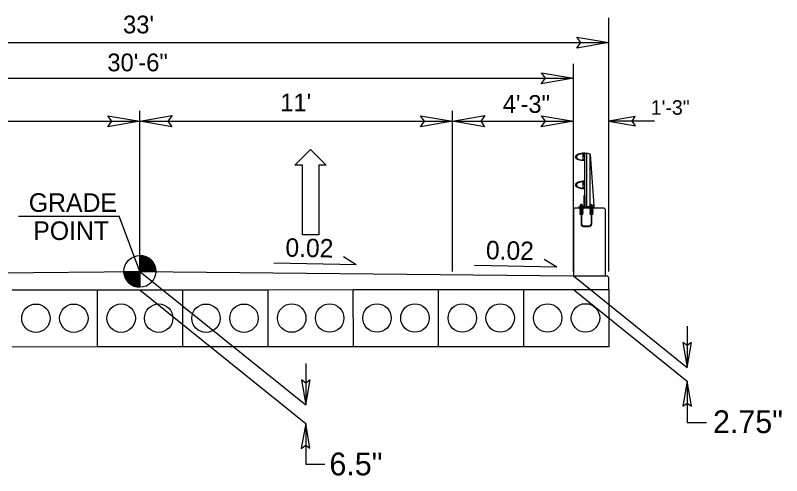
# Model space of a CAD drawing. Extents: x 1733676 to 1734289, y 540979 to 541226.
# Drawn here: x 1734262.38 to 1734289.33, y 541078.06 to 541094.25 of the extents above; entities that cross this region are included whole.
import ezdxf

# ---------------------------------------------------------------- set-up
doc = ezdxf.new("R2010")
doc.units = 0
for name, color, linetype in [('Prop Dimension', 7, 'Continuous'), ('Prop Lane Arrow CELL', 7, 'Continuous'), ('Prop Terminator CELL', 7, 'Continuous'), ('Typical Bridge Rail Two Bar CELL', 7, 'Continuous'), ('Typical Grade Point Symbol CELL', 7, 'Continuous'), ('Typical Pavement Slope CELL', 7, 'Continuous'), ('Typical Pavement Slope Information CELL', 7, 'Continuous'), ('Typical Slope Point Local CELL', 7, 'Continuous'), ('Typical Terminator CELL', 7, 'Continuous'), ('Typical Text Grade Point CELL', 7, 'Continuous')]:
    doc.layers.add(name, color=color, linetype=linetype)

msp = doc.modelspace()

# ---------------------------------------------------------------- linework, layer by layer
at = {"layer": 'Prop Dimension'}
for p, q in [((1734283.259, 541085.248), (1734283.259, 541094.168)), ((1734250.259, 541093.296), (1734283.259, 541093.296)), ((1734282.009, 541085.248), (1734282.009, 541092.543)), ((1734251.509, 541092.043), (1734282.009, 541092.043)), ((1734266.759, 541085.248), (1734266.759, 541090.891)), ((1734277.759, 541085.248), (1734277.759, 541090.891)), ((1734255.759, 541090.531), (1734266.759, 541090.531)), ((1734266.759, 541090.531), (1734277.759, 541090.531)), ((1734277.759, 541090.531), (1734282.009, 541090.531)), ((1734284.864, 541090.531), (1734283.259, 541090.531)), ((1734262.486, 541087.185), (1734266.024, 541087.185)), ((1734266.759, 541085.248), (1734266.024, 541087.185)), ((1734266.759, 541085.248), (1734272.591, 541080.549)), ((1734282.009, 541085.092), (1734286.01, 541081.869)), ((1734262.266, 541084.599), (1734265.266, 541084.601)), ((1734265.266, 541084.601), (1734268.266, 541084.603)), ((1734265.267, 541082.601), (1734265.266, 541084.601)), ((1734265.267, 541082.601), (1734265.266, 541084.601)), ((1734266.759, 541084.602), (1734272.591, 541079.903)), ((1734268.266, 541084.603), (1734271.266, 541084.604)), ((1734268.267, 541082.603), (1734268.266, 541084.603)), ((1734268.267, 541082.603), (1734268.266, 541084.603)), ((1734271.266, 541084.604), (1734274.266, 541084.606)), ((1734271.267, 541082.604), (1734271.266, 541084.604)), ((1734271.267, 541082.604), (1734271.266, 541084.604)), ((1734274.266, 541084.606), (1734277.266, 541084.608)), ((1734274.267, 541082.606), (1734274.266, 541084.606)), ((1734274.267, 541082.606), (1734274.266, 541084.606)), ((1734277.266, 541084.608), (1734280.266, 541084.61)), ((1734277.267, 541082.608), (1734277.266, 541084.608)), ((1734277.267, 541082.608), (1734277.266, 541084.608)), ((1734280.266, 541084.61), (1734283.266, 541084.611)), ((1734280.267, 541082.61), (1734280.266, 541084.61)), ((1734280.267, 541082.61), (1734280.266, 541084.61)), ((1734282.009, 541084.611), (1734286.01, 541081.387)), ((1734283.267, 541082.611), (1734283.266, 541084.611)), ((1734286.01, 541083.321), (1734286.01, 541081.869)), ((1734262.267, 541082.599), (1734265.267, 541082.601)), ((1734265.267, 541082.601), (1734268.267, 541082.603)), ((1734268.267, 541082.603), (1734271.267, 541082.604)), ((1734271.267, 541082.604), (1734274.267, 541082.606)), ((1734274.267, 541082.606), (1734277.267, 541082.608)), ((1734277.267, 541082.608), (1734280.267, 541082.61)), ((1734280.267, 541082.61), (1734283.267, 541082.611)), ((1734272.591, 541082.002), (1734272.591, 541080.549)), ((1734286.01, 541081.387), (1734286.01, 541079.935)), ((1734272.591, 541079.903), (1734272.591, 541078.45)), ((1734286.01, 541079.935), (1734286.687, 541079.935)), ((1734273.268, 541078.45), (1734272.591, 541078.45))]:
    msp.add_line(p, q, dxfattribs=at)
for centre in [(1734263.1, 541083.6), (1734264.433, 541083.6), (1734266.1, 541083.601), (1734267.418, 541083.601), (1734269.085, 541083.6), (1734270.418, 541083.6), (1734272.1, 541083.605), (1734273.433, 541083.606), (1734275.1, 541083.607), (1734276.433, 541083.607), (1734278.1, 541083.608), (1734279.433, 541083.609), (1734281.1, 541083.61), (1734282.433, 541083.611)]:
    msp.add_circle(centre, 0.5, dxfattribs=at)
at = {"layer": 'Prop Lane Arrow CELL'}
for p, q in [((1734272.213, 541088.984), (1734272.755, 541089.536)), ((1734272.755, 541089.536), (1734273.315, 541088.984)), ((1734272.475, 541088.984), (1734272.213, 541088.984)), ((1734272.475, 541086.534), (1734272.475, 541088.984)), ((1734273.315, 541088.984), (1734273.053, 541088.984)), ((1734273.053, 541088.984), (1734273.053, 541086.534)), ((1734273.053, 541086.534), (1734272.475, 541086.534))]:
    msp.add_line(p, q, dxfattribs=at)
at = {"layer": 'Prop Terminator CELL'}
for points in [[(1734282.134, 541093.489), (1734283.259, 541093.296), (1734282.128, 541093.096), (1734282.271, 541093.296)], [(1734280.884, 541092.236), (1734282.009, 541092.043), (1734280.878, 541091.843), (1734281.021, 541092.043)], [(1734265.634, 541090.725), (1734266.759, 541090.531), (1734265.628, 541090.331), (1734265.771, 541090.531)], [(1734267.884, 541090.338), (1734266.759, 541090.531), (1734267.89, 541090.731), (1734267.746, 541090.531)], [(1734276.634, 541090.725), (1734277.759, 541090.531), (1734276.628, 541090.331), (1734276.771, 541090.531)], [(1734278.884, 541090.338), (1734277.759, 541090.531), (1734278.89, 541090.731), (1734278.746, 541090.531)], [(1734280.884, 541090.725), (1734282.009, 541090.531), (1734280.878, 541090.331), (1734281.021, 541090.531)], [(1734284.184, 541090.691), (1734283.259, 541090.531), (1734284.19, 541090.367), (1734284.071, 541090.531)]]:
    msp.add_lwpolyline(points, close=True, dxfattribs=at)
at = {"layer": 'Typical Bridge Rail Two Bar CELL'}
for p, q in [((1734282.346, 541089.377), (1734282.346, 541089.275)), ((1734282.409, 541089.409), (1734282.484, 541089.409)), ((1734282.409, 541087.525), (1734282.409, 541089.409)), ((1734282.598, 541089.371), (1734282.484, 541089.409)), ((1734282.484, 541087.525), (1734282.484, 541089.409)), ((1734282.598, 541087.525), (1734282.598, 541089.371)), ((1734282.598, 541089.371), (1734282.729, 541087.563)), ((1734282.346, 541089.173), (1734282.346, 541089.275)), ((1734282.598, 541088.507), (1734282.602, 541088.507)), ((1734282.346, 541088.39), (1734282.346, 541088.288)), ((1734282.346, 541088.186), (1734282.346, 541088.288)), ((1734282.01, 541087.439), (1734282.059, 541087.487)), ((1734282.01, 541087.439), (1734282.01, 541085.094)), ((1734282.059, 541087.487), (1734283.079, 541087.487)), ((1734282.237, 541087.451), (1734282.337, 541087.451)), ((1734282.237, 541087.44), (1734282.337, 541087.44)), ((1734282.237, 541087.407), (1734282.279, 541087.407)), ((1734282.237, 541087.396), (1734282.279, 541087.396)), ((1734282.259, 541087.429), (1734282.279, 541087.429)), ((1734282.259, 541087.418), (1734282.279, 541087.418)), ((1734282.262, 541087.451), (1734282.262, 541087.535)), ((1734282.264, 541087.576), (1734282.264, 541087.611)), ((1734282.264, 541087.611), (1734282.307, 541087.611)), ((1734282.279, 541087.429), (1734282.296, 541087.429)), ((1734282.279, 541087.429), (1734282.279, 541086.898)), ((1734282.296, 541087.429), (1734282.315, 541087.429)), ((1734282.296, 541087.429), (1734282.296, 541086.898)), ((1734282.296, 541087.418), (1734282.315, 541087.418)), ((1734282.296, 541087.407), (1734282.337, 541087.407)), ((1734282.296, 541087.396), (1734282.337, 541087.396)), ((1734282.307, 541087.611), (1734282.307, 541087.576)), ((1734282.309, 541087.451), (1734282.309, 541087.535)), ((1734282.586, 541087.451), (1734282.686, 541087.451)), ((1734282.586, 541087.44), (1734282.686, 541087.44)), ((1734282.586, 541087.407), (1734282.628, 541087.407)), ((1734282.586, 541087.396), (1734282.628, 541087.396)), ((1734282.608, 541087.429), (1734282.628, 541087.429)), ((1734282.608, 541087.418), (1734282.628, 541087.418)), ((1734282.613, 541087.566), (1734282.613, 541087.601)), ((1734282.613, 541087.601), (1734282.656, 541087.601)), ((1734282.613, 541087.442), (1734282.613, 541087.525)), ((1734282.628, 541087.429), (1734282.644, 541087.429)), ((1734282.628, 541087.429), (1734282.628, 541086.898)), ((1734282.644, 541087.429), (1734282.664, 541087.429)), ((1734282.644, 541087.429), (1734282.644, 541086.898)), ((1734282.644, 541087.418), (1734282.664, 541087.418)), ((1734282.644, 541087.407), (1734282.686, 541087.407)), ((1734282.644, 541087.396), (1734282.686, 541087.396)), ((1734282.656, 541087.601), (1734282.656, 541087.566)), ((1734282.657, 541087.442), (1734282.657, 541087.525)), ((1734282.726, 541087.584), (1734282.726, 541087.617)), ((1734282.729, 541087.525), (1734282.729, 541087.563)), ((1734283.079, 541087.487), (1734283.128, 541087.439)), ((1734283.128, 541087.439), (1734283.128, 541085.094)), ((1734282.237, 541087.362), (1734282.279, 541087.362)), ((1734282.237, 541087.351), (1734282.279, 541087.351)), ((1734282.237, 541087.318), (1734282.279, 541087.318)), ((1734282.237, 541087.307), (1734282.279, 541087.307)), ((1734282.237, 541087.274), (1734282.279, 541087.274)), ((1734282.237, 541087.263), (1734282.279, 541087.263)), ((1734282.259, 541087.384), (1734282.279, 541087.384)), ((1734282.259, 541087.373), (1734282.279, 541087.373)), ((1734282.259, 541087.34), (1734282.279, 541087.34)), ((1734282.259, 541087.329), (1734282.279, 541087.329)), ((1734282.259, 541087.296), (1734282.279, 541087.296)), ((1734282.259, 541087.285), (1734282.279, 541087.285)), ((1734282.296, 541087.384), (1734282.315, 541087.384)), ((1734282.296, 541087.373), (1734282.315, 541087.373)), ((1734282.296, 541087.362), (1734282.337, 541087.362)), ((1734282.296, 541087.351), (1734282.337, 541087.351)), ((1734282.296, 541087.34), (1734282.315, 541087.34)), ((1734282.296, 541087.329), (1734282.315, 541087.329)), ((1734282.296, 541087.318), (1734282.337, 541087.318)), ((1734282.296, 541087.307), (1734282.337, 541087.307)), ((1734282.296, 541087.296), (1734282.315, 541087.296)), ((1734282.296, 541087.285), (1734282.315, 541087.285)), ((1734282.296, 541087.274), (1734282.337, 541087.274)), ((1734282.296, 541087.263), (1734282.337, 541087.263)), ((1734282.586, 541087.362), (1734282.628, 541087.362)), ((1734282.586, 541087.351), (1734282.628, 541087.351)), ((1734282.586, 541087.318), (1734282.628, 541087.318)), ((1734282.586, 541087.307), (1734282.628, 541087.307)), ((1734282.586, 541087.274), (1734282.628, 541087.274)), ((1734282.586, 541087.263), (1734282.628, 541087.263)), ((1734282.608, 541087.384), (1734282.628, 541087.384)), ((1734282.608, 541087.373), (1734282.628, 541087.373)), ((1734282.608, 541087.34), (1734282.628, 541087.34)), ((1734282.608, 541087.329), (1734282.628, 541087.329)), ((1734282.608, 541087.296), (1734282.628, 541087.296)), ((1734282.608, 541087.285), (1734282.628, 541087.285)), ((1734282.644, 541087.384), (1734282.664, 541087.384)), ((1734282.644, 541087.373), (1734282.664, 541087.373)), ((1734282.644, 541087.362), (1734282.686, 541087.362)), ((1734282.644, 541087.351), (1734282.686, 541087.351)), ((1734282.644, 541087.34), (1734282.664, 541087.34)), ((1734282.644, 541087.329), (1734282.664, 541087.329)), ((1734282.644, 541087.318), (1734282.686, 541087.318)), ((1734282.644, 541087.307), (1734282.686, 541087.307)), ((1734282.644, 541087.296), (1734282.664, 541087.296)), ((1734282.644, 541087.285), (1734282.664, 541087.285)), ((1734282.644, 541087.274), (1734282.686, 541087.274)), ((1734282.644, 541087.263), (1734282.686, 541087.263)), ((1734282.349, 541086.845), (1734282.574, 541086.845)), ((1734282.349, 541086.829), (1734282.574, 541086.829)), ((1734282.01, 541085.094), (1734283.119, 541085.094)), ((1734283.119, 541085.094), (1734283.2, 541085.094)), ((1734283.248, 541085.041), (1734283.2, 541085.094))]:
    msp.add_line(p, q, dxfattribs=at)
for points in [[(1734282.409, 541089.145), (1734282.409, 541089.194), (1734282.389, 541089.194), (1734282.389, 541089.185), (1734282.39, 541089.185), (1734282.39, 541089.165), (1734282.358, 541089.165), (1734282.354, 541089.196), (1734282.354, 541089.275), (1734282.354, 541089.354), (1734282.358, 541089.385), (1734282.39, 541089.385), (1734282.39, 541089.365), (1734282.389, 541089.365), (1734282.389, 541089.357), (1734282.409, 541089.357), (1734282.409, 541089.406)], [(1734282.409, 541088.157), (1734282.409, 541088.206), (1734282.389, 541088.206), (1734282.389, 541088.198), (1734282.39, 541088.198), (1734282.39, 541088.178), (1734282.358, 541088.178), (1734282.354, 541088.209), (1734282.354, 541088.288), (1734282.354, 541088.367), (1734282.358, 541088.398), (1734282.39, 541088.398), (1734282.39, 541088.378), (1734282.389, 541088.378), (1734282.389, 541088.37), (1734282.409, 541088.37), (1734282.409, 541088.418)], [(1734282.216, 541087.487), (1734282.216, 541087.535), (1734282.39, 541087.535), (1734282.39, 541087.921), (1734282.409, 541087.921), (1734282.409, 541087.525), (1734282.72, 541087.525), (1734282.72, 541087.553), (1734282.729, 541087.553), (1734282.729, 541087.487), (1734282.579, 541087.487), (1734282.579, 541087.514), (1734282.428, 541087.514), (1734282.428, 541087.487), (1734282.216, 541087.487)], [(1734282.237, 541087.451), (1734282.237, 541087.44), (1734282.259, 541087.429), (1734282.259, 541087.418), (1734282.237, 541087.407), (1734282.237, 541087.396), (1734282.259, 541087.384), (1734282.259, 541087.373), (1734282.237, 541087.362), (1734282.237, 541087.351), (1734282.259, 541087.34), (1734282.259, 541087.329), (1734282.237, 541087.318), (1734282.237, 541087.307), (1734282.259, 541087.296), (1734282.259, 541087.285), (1734282.237, 541087.274), (1734282.237, 541087.263)], [(1734282.242, 541087.534), (1734282.242, 541087.543), (1734282.285, 541087.543), (1734282.328, 541087.543), (1734282.328, 541087.534)], [(1734282.254, 541087.543), (1734282.254, 541087.57), (1734282.259, 541087.575), (1734282.312, 541087.575), (1734282.318, 541087.57), (1734282.318, 541087.543), (1734282.254, 541087.543), (1734282.275, 541087.543), (1734282.275, 541087.57), (1734282.27, 541087.575), (1734282.275, 541087.57), (1734282.28, 541087.575), (1734282.292, 541087.575), (1734282.297, 541087.57), (1734282.297, 541087.543), (1734282.297, 541087.57), (1734282.302, 541087.575)], [(1734282.337, 541087.451), (1734282.337, 541087.44), (1734282.315, 541087.429), (1734282.315, 541087.418), (1734282.337, 541087.407), (1734282.337, 541087.396), (1734282.315, 541087.384), (1734282.315, 541087.373), (1734282.337, 541087.362), (1734282.337, 541087.351), (1734282.315, 541087.34), (1734282.315, 541087.329), (1734282.337, 541087.318), (1734282.337, 541087.307), (1734282.315, 541087.296), (1734282.315, 541087.285), (1734282.337, 541087.274), (1734282.337, 541087.263)], [(1734282.586, 541087.451), (1734282.586, 541087.44), (1734282.608, 541087.429), (1734282.608, 541087.418), (1734282.586, 541087.407), (1734282.586, 541087.396), (1734282.608, 541087.384), (1734282.608, 541087.373), (1734282.586, 541087.362), (1734282.586, 541087.351), (1734282.608, 541087.34), (1734282.608, 541087.329), (1734282.586, 541087.318), (1734282.586, 541087.307), (1734282.608, 541087.296), (1734282.608, 541087.285), (1734282.586, 541087.274), (1734282.586, 541087.263)], [(1734282.592, 541087.525), (1734282.592, 541087.533), (1734282.635, 541087.533), (1734282.678, 541087.533), (1734282.678, 541087.525)], [(1734282.603, 541087.533), (1734282.603, 541087.56), (1734282.608, 541087.566), (1734282.661, 541087.566), (1734282.667, 541087.56), (1734282.667, 541087.533), (1734282.603, 541087.533), (1734282.624, 541087.533), (1734282.624, 541087.56), (1734282.619, 541087.566), (1734282.624, 541087.56), (1734282.629, 541087.566), (1734282.64, 541087.566), (1734282.646, 541087.56), (1734282.646, 541087.533), (1734282.646, 541087.56), (1734282.651, 541087.566)], [(1734282.686, 541087.451), (1734282.686, 541087.44), (1734282.664, 541087.429), (1734282.664, 541087.418), (1734282.686, 541087.407), (1734282.686, 541087.396), (1734282.664, 541087.384), (1734282.664, 541087.373), (1734282.686, 541087.362), (1734282.686, 541087.351), (1734282.664, 541087.34), (1734282.664, 541087.329), (1734282.686, 541087.318), (1734282.686, 541087.307), (1734282.664, 541087.296), (1734282.664, 541087.285), (1734282.686, 541087.274), (1734282.686, 541087.263)]]:
    msp.add_lwpolyline(points, dxfattribs=at)
for centre in [(1734282.246, 541087.29), (1734282.677, 541087.29)]:
    msp.add_circle(centre, 0.00834, dxfattribs=at)
for centre, radius, start, end in [((1734282.338, 541089.377), 0.00783, 0, 90), ((1734282.338, 541089.173), 0.00783, 270, 360), ((1734282.338, 541088.39), 0.00783, 0, 90), ((1734282.338, 541088.186), 0.00783, 270, 360), ((1734282.349, 541086.898), 0.07, 180, 270), ((1734282.349, 541086.898), 0.0534, 180, 270), ((1734282.574, 541086.898), 0.0534, 270, 0), ((1734282.574, 541086.898), 0.07, 270, 0)]:
    msp.add_arc(centre, radius, start, end, dxfattribs=at)
for centre, major_axis, ratio, start_param, end_param in [((1734282.409, 541089.275), (-0.334, 0), 0.39036, 4.712404, 6.283584), ((1734282.338, 541089.275), (-0.222, 0), 0.495501, 4.712489, 6.283652), ((1734282.409, 541089.275), (-0.334, 0), 0.39036, 0.000398, 1.570782), ((1734282.338, 541089.275), (-0.222, 0), 0.495501, 0.000467, 1.570696), ((1734282.409, 541088.288), (-0.334, 0), 0.39036, 4.712404, 6.283584), ((1734282.409, 541088.288), (-0.334, 0), 0.39036, 0.000398, 1.570782), ((1734282.338, 541088.288), (-0.222, 0), 0.495501, 4.712489, 6.283652), ((1734282.338, 541088.288), (-0.222, 0), 0.495501, 0.000467, 1.570696)]:
    msp.add_ellipse(centre, major_axis=major_axis, ratio=ratio, start_param=start_param, end_param=end_param, dxfattribs=at)
at = {"layer": 'Typical Grade Point Symbol CELL'}
for p, q in [((1734266.759, 541085.248), (1734266.759, 541085.807)), ((1734266.199, 541085.248), (1734266.759, 541085.248)), ((1734266.758, 541084.688), (1734266.759, 541085.248)), ((1734266.759, 541085.248), (1734266.758, 541084.688)), ((1734267.318, 541085.248), (1734266.759, 541085.248))]:
    msp.add_line(p, q, dxfattribs=at)
for points in [[(1734266.764, 541085.807), (1734266.764, 541085.807), (1734266.764, 541085.248)], [(1734266.775, 541085.807), (1734266.775, 541085.248)], [(1734266.786, 541085.806), (1734266.786, 541085.248)], [(1734266.797, 541085.806), (1734266.797, 541085.248)], [(1734266.809, 541085.805), (1734266.809, 541085.248)], [(1734266.82, 541085.803), (1734266.82, 541085.248)], [(1734266.831, 541085.802), (1734266.831, 541085.248)], [(1734266.842, 541085.801), (1734266.842, 541085.248)], [(1734266.853, 541085.8), (1734266.853, 541085.248)], [(1734266.865, 541085.797), (1734266.865, 541085.248)], [(1734266.876, 541085.795), (1734266.876, 541085.248)], [(1734266.887, 541085.792), (1734266.887, 541085.248)], [(1734266.898, 541085.79), (1734266.898, 541085.248)], [(1734266.909, 541085.786), (1734266.909, 541085.248)], [(1734266.921, 541085.784), (1734266.921, 541085.248)], [(1734266.932, 541085.78), (1734266.932, 541085.248)], [(1734266.943, 541085.776), (1734266.943, 541085.248)], [(1734266.954, 541085.772), (1734266.954, 541085.248)], [(1734266.965, 541085.767), (1734266.965, 541085.248)], [(1734266.977, 541085.762), (1734266.977, 541085.248)], [(1734266.988, 541085.757), (1734266.988, 541085.248)], [(1734266.999, 541085.752), (1734266.999, 541085.248)], [(1734267.01, 541085.748), (1734267.01, 541085.248)], [(1734267.021, 541085.741), (1734267.021, 541085.248)], [(1734267.032, 541085.735), (1734267.032, 541085.248)], [(1734267.044, 541085.729), (1734267.044, 541085.248)], [(1734267.055, 541085.723), (1734267.055, 541085.248)], [(1734267.066, 541085.715), (1734267.066, 541085.248)], [(1734267.077, 541085.708), (1734267.077, 541085.248)], [(1734267.088, 541085.699), (1734267.088, 541085.248)], [(1734267.1, 541085.692), (1734267.1, 541085.248)], [(1734267.111, 541085.683), (1734267.111, 541085.248)], [(1734267.122, 541085.673), (1734267.122, 541085.248)], [(1734267.133, 541085.663), (1734267.133, 541085.248)], [(1734267.144, 541085.653), (1734267.144, 541085.248)], [(1734267.156, 541085.642), (1734267.156, 541085.248)], [(1734267.167, 541085.631), (1734267.167, 541085.248)], [(1734267.178, 541085.618), (1734267.178, 541085.248)], [(1734267.189, 541085.605), (1734267.189, 541085.248)], [(1734267.2, 541085.591), (1734267.2, 541085.248)], [(1734267.212, 541085.576), (1734267.212, 541085.248)], [(1734267.223, 541085.56), (1734267.223, 541085.248)], [(1734267.234, 541085.542), (1734267.234, 541085.248)], [(1734267.245, 541085.524), (1734267.245, 541085.248)], [(1734267.256, 541085.504), (1734267.256, 541085.248)], [(1734266.202, 541085.248), (1734266.202, 541085.187)], [(1734266.213, 541085.248), (1734266.213, 541085.121)], [(1734266.224, 541085.248), (1734266.224, 541085.081)], [(1734266.235, 541085.248), (1734266.235, 541085.048)], [(1734266.247, 541085.248), (1734266.247, 541085.021)], [(1734266.258, 541085.248), (1734266.258, 541084.998)], [(1734266.269, 541085.248), (1734266.269, 541084.977)], [(1734266.28, 541085.248), (1734266.28, 541084.957)], [(1734266.291, 541085.248), (1734266.291, 541084.939)], [(1734266.303, 541085.248), (1734266.303, 541084.923)], [(1734266.314, 541085.248), (1734266.314, 541084.908)], [(1734266.325, 541085.248), (1734266.325, 541084.895)], [(1734266.336, 541085.248), (1734266.336, 541084.881)], [(1734266.347, 541085.248), (1734266.347, 541084.868)], [(1734266.359, 541085.248), (1734266.359, 541084.856)], [(1734266.37, 541085.248), (1734266.37, 541084.845)], [(1734266.381, 541085.248), (1734266.381, 541084.835)], [(1734266.392, 541085.248), (1734266.392, 541084.825)], [(1734266.403, 541085.248), (1734266.403, 541084.815)], [(1734266.415, 541085.248), (1734266.415, 541084.806)], [(1734266.426, 541085.248), (1734266.426, 541084.798)], [(1734266.437, 541085.248), (1734266.437, 541084.79)], [(1734266.448, 541085.248), (1734266.448, 541084.783)], [(1734266.459, 541085.248), (1734266.459, 541084.775)], [(1734266.47, 541085.248), (1734266.47, 541084.768)], [(1734266.482, 541085.248), (1734266.482, 541084.762)], [(1734266.493, 541085.248), (1734266.493, 541084.755)], [(1734266.504, 541085.248), (1734266.504, 541084.749)], [(1734266.515, 541085.248), (1734266.515, 541084.744)], [(1734266.526, 541085.248), (1734266.526, 541084.739)], [(1734266.538, 541085.248), (1734266.538, 541084.734)], [(1734266.549, 541085.248), (1734266.549, 541084.729)], [(1734266.56, 541085.248), (1734266.56, 541084.724)], [(1734266.571, 541085.248), (1734266.571, 541084.721)], [(1734266.582, 541085.248), (1734266.582, 541084.717)], [(1734266.594, 541085.248), (1734266.594, 541084.713)], [(1734266.605, 541085.248), (1734266.605, 541084.711)], [(1734266.616, 541085.248), (1734266.616, 541084.707)], [(1734266.627, 541085.248), (1734266.627, 541084.704)], [(1734266.638, 541085.248), (1734266.638, 541084.702)], [(1734266.65, 541085.248), (1734266.65, 541084.699)], [(1734266.661, 541085.248), (1734266.661, 541084.697)], [(1734266.672, 541085.248), (1734266.672, 541084.696)], [(1734266.683, 541085.248), (1734266.683, 541084.693)], [(1734266.694, 541085.248), (1734266.694, 541084.692)], [(1734266.705, 541085.248), (1734266.705, 541084.691)], [(1734266.717, 541085.248), (1734266.717, 541084.689)], [(1734266.728, 541085.248), (1734266.728, 541084.689)], [(1734266.739, 541085.248), (1734266.739, 541084.688)], [(1734266.75, 541085.248), (1734266.75, 541084.688), (1734266.75, 541084.688)], [(1734267.267, 541085.48), (1734267.267, 541085.248)], [(1734267.279, 541085.454), (1734267.279, 541085.248)], [(1734267.29, 541085.423), (1734267.29, 541085.248)], [(1734267.301, 541085.384), (1734267.301, 541085.248)], [(1734267.312, 541085.327), (1734267.312, 541085.248)]]:
    msp.add_lwpolyline(points, dxfattribs=at)
msp.add_circle((1734266.758, 541085.248), 0.559, dxfattribs=at)
for start, end in [(359.9905, 89.9905), (179.9905, 269.9905)]:
    msp.add_arc((1734266.758, 541085.248), 0.559, start, end, dxfattribs=at)
at = {"layer": 'Typical Pavement Slope CELL'}
for p, q in [((1734251.51, 541085.092), (1734266.759, 541085.248)), ((1734266.759, 541085.248), (1734282.009, 541085.092)), ((1734283.248, 541085.041), (1734283.248, 541084.611))]:
    msp.add_line(p, q, dxfattribs=at)
at = {"layer": 'Typical Pavement Slope Information CELL'}
for p, q in [((1734274.37, 541085.483), (1734271.475, 541085.54)), ((1734274.37, 541085.483), (1734273.92, 541085.754)), ((1734281.423, 541085.392), (1734280.974, 541085.663)), ((1734281.423, 541085.392), (1734278.528, 541085.45))]:
    msp.add_line(p, q, dxfattribs=at)
at = {"layer": 'Typical Terminator CELL'}
for points in [[(1734285.859, 541082.747), (1734286.01, 541081.869), (1734286.166, 541082.752), (1734286.01, 541082.64)], [(1734272.44, 541081.428), (1734272.591, 541080.549), (1734272.747, 541081.433), (1734272.591, 541081.321)], [(1734286.161, 541080.509), (1734286.01, 541081.387), (1734285.854, 541080.504), (1734286.01, 541080.616)], [(1734272.742, 541079.024), (1734272.591, 541079.903), (1734272.435, 541079.019), (1734272.591, 541079.132)]]:
    msp.add_lwpolyline(points, close=True, dxfattribs=at)

# ---------------------------------------------------------------- texts
at = {"layer": 'Prop Dimension'}
msp.add_text('6.5"', height=0.8, rotation=360, dxfattribs=at).set_placement((1734273.425, 541078.074))
at = {"layer": 'Typical Pavement Slope Information CELL'}
for p in [(1734271.873, 541085.767), (1734278.926, 541085.677)]:
    msp.add_text('0.02', height=0.6476, rotation=358.8543, dxfattribs=at).set_placement(p)
at = {"layer": 'Typical Slope Point Local CELL'}
for s, height, p in [("33'", 0.6249, (1734266.166, 541093.62)), ('30\'-6"', 0.6249, (1734265.613, 541092.286)), ("11'", 0.6249, (1734271.695, 541090.878)), ('4\'-3"', 0.6249, (1734279.521, 541090.823)), ('1\'-3"', 0.5141, (1734284.73, 541090.756)), ('2.75"', 0.8, (1734286.918, 541079.56))]:
    msp.add_text(s, height=height, rotation=360, dxfattribs=at).set_placement(p)
at = {"layer": 'Typical Text Grade Point CELL'}
for s, p in [('GRADE', (1734262.85, 541087.342)), ('POINT', (1734263.007, 541086.353))]:
    msp.add_text(s, height=0.6525, dxfattribs=at).set_placement(p)

doc.saveas('drawing.dxf')
